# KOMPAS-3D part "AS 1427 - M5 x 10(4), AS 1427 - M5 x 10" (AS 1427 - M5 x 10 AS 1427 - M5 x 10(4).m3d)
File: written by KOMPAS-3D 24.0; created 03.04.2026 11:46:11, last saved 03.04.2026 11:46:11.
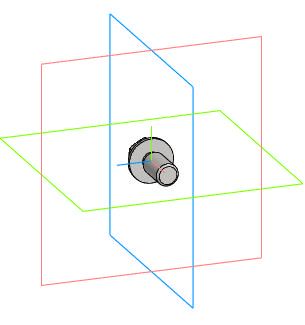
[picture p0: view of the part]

Document properties: Автор: R2D2; Полное имя файла: E:\Работа\Зайцев\Аксессуары для пневмоприводов\Ручной дублер DN.ru\MON1-250-T26-ISO Ручной дублер DN.ru\исходные материалы\AS 1427 - M5 x 10 AS 1427 - M5 x 10(4).m3d

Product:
- Body: Solid1  | qty 1
- Part/product: AS 1427 - M5 x 10(4)  | designation AS 1427 - M5 x 10
    Комментарий: Винты мелкие крепежные   метрические ISO
    additional columns: Сталь, мягкая

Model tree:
1. Solid1  (labels: Solid1)

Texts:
  AS 1427 - M5 x 10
